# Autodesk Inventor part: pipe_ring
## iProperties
Shininess: 64.0
Length Units: 11269
Angle Units: 11279
Time Units: 11290
Mass Units: 11283
Length Display Precision: 3
Angle Display Precision: 2
Compacted: True
Part Number: pipe_ring
Document SubType Name: Modeling
Created: 2004-07
Designer: Peter
Manufacturer: Standard
Standards Organization: Custom
Density: 0.0
Volumn: 0.0
Area: 0.0
PropertySet Name: Model Information
Control State: 0
Master: False
Checked Out: False
Author: Peter
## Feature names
1. Revolution3
2. Hole4
3. Hole5
